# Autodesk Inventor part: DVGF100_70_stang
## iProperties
Created: 2010-04
Part Number: DVGF100_70_stang
Document SubType Name: Modeling
Designer: TB
Mass: 1207.35 g
Surface Area: 811.554 cm^2
Volume: 1207.35 cm^3
Density: 1 g/cm^3
Author: TB
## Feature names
1. Revolution1
2. Fillet1
3. Revolution2
4. Extrusion1
5. Extrusion2
6. Chamfer1
7. Fillet2
8. Chamfer3
